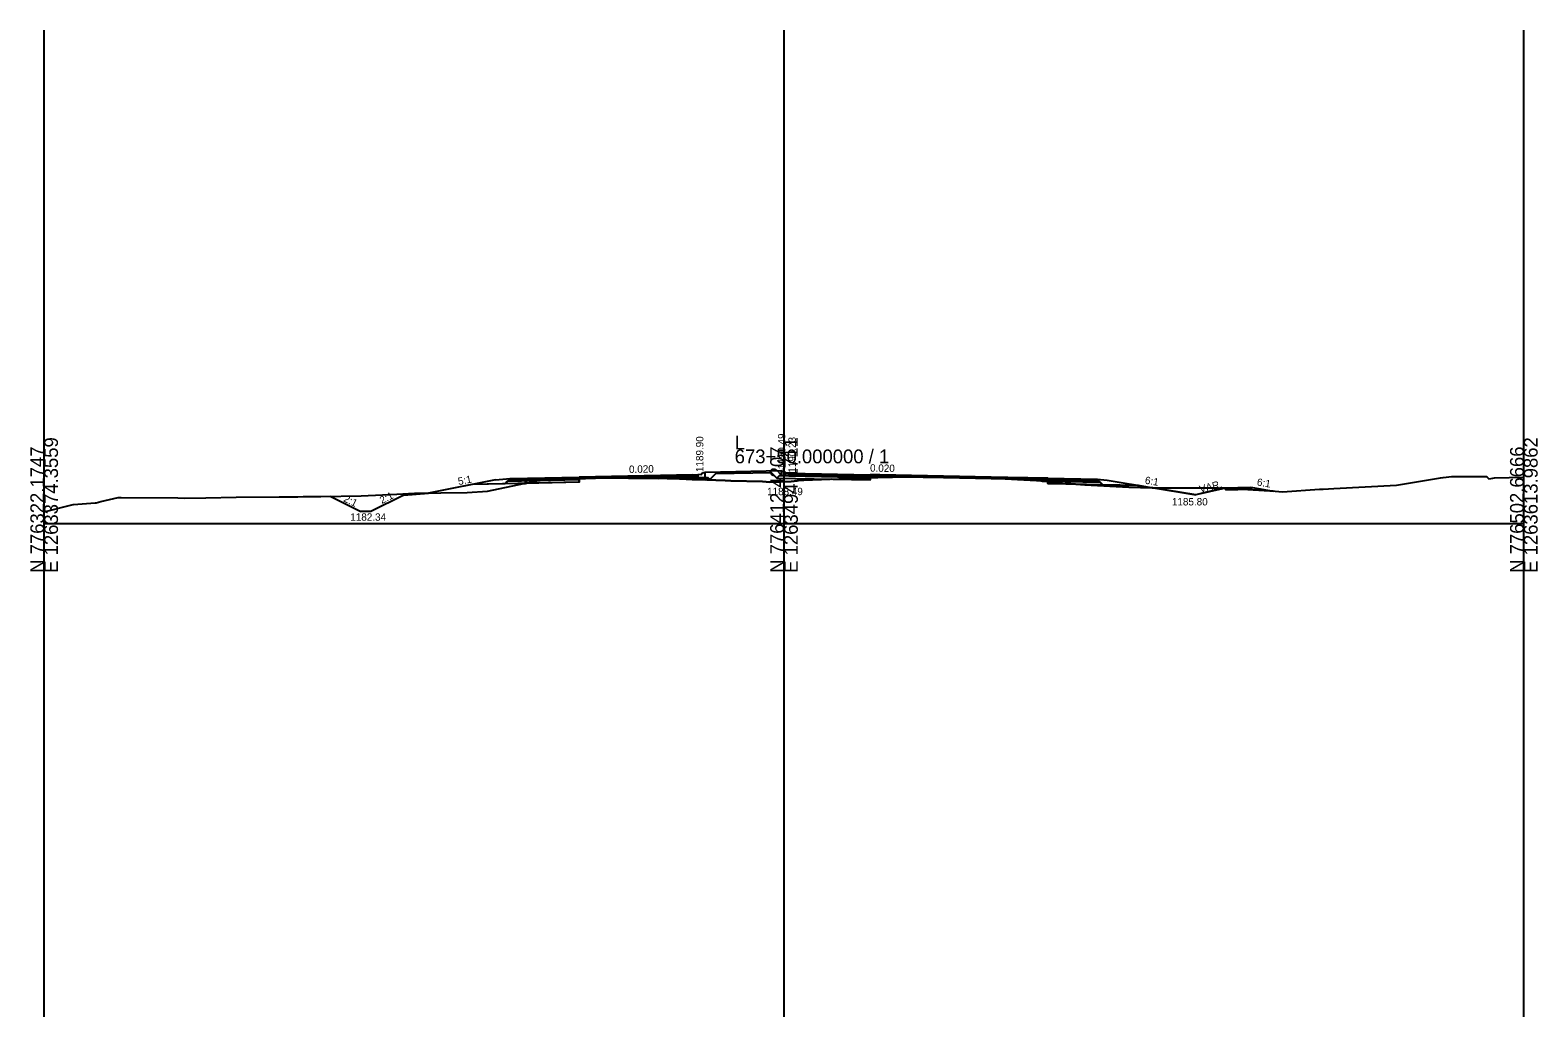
# Model space of a CAD drawing. Extents: x -41 to 1262860, y -100 to 777489.
# Drawn here: x 497.2 to 802.8, y 335 to 535 of the extents above; entities that cross this region are included whole.
import ezdxf

# ---------------------------------------------------------------- set-up
doc = ezdxf.new("R2010")
doc.units = 0
for name, color, linetype in [('Exist Cross Section Cell', 7, 'Continuous'), ('Exist XS Center Line Elevation Label', 7, 'Continuous'), ('Exist XS Ground Line', 7, 'Continuous'), ('Prop CMT Pvmt Concrete', 7, 'Continuous'), ('Prop CMT Pvmt Course 1', 7, 'Continuous'), ('Prop CMT Pvmt Course 4', 7, 'Continuous'), ('Prop CMT Pvmt Surface', 7, 'Continuous'), ('Prop CMT Shld Paved Course 1', 7, 'Continuous'), ('Prop CMT Shld Paved Course 2', 7, 'Continuous'), ('Prop CMT Shld Paved Course 4', 7, 'Continuous'), ('Prop CMT Subgrade Earthwork', 7, 'Continuous'), ('Prop Conc Curb and Gutter', 7, 'Continuous'), ('Prop Conc Island Cover', 7, 'Continuous'), ('Prop XS Ditch Standard Text', 7, 'Continuous'), ('Prop XS Earthwork Shape', 7, 'Continuous'), ('Prop XS Elevation Labels', 7, 'Continuous'), ('Prop XS Exc Vertical Line 1', 7, 'Continuous'), ('Prop XS Exc Vertical Line 2', 7, 'Continuous'), ('Prop XS Exc Vertical Line 3', 7, 'Continuous'), ('Prop XS Finish Grade', 7, 'Continuous'), ('Prop XS Hydro Elevations', 7, 'Continuous'), ('Prop XS SE Text', 7, 'Continuous'), ('Prop XS Side Slope Text', 7, 'Continuous'), ('Scratch_Level_1', 7, 'Continuous'), ('Scratch_Level_4', 7, 'Continuous'), ('Scratch_Level_6', 7, 'Continuous')]:
    doc.layers.add(name, color=color, linetype=linetype)

msp = doc.modelspace()

# ---------------------------------------------------------------- linework, layer by layer
at = {"layer": 'Exist Cross Section Cell'}
for p, q in [((650, 435), (650, 450)), ((500, 435), (650, 435)), ((650, 435), (800, 435))]:
    msp.add_line(p, q, dxfattribs=at)
at = {"layer": 'Exist XS Ground Line'}
msp.add_lwpolyline([(500, 437.38), (505.86, 438.85), (505.98, 438.88), (510.34, 439.19), (510.56, 439.22), (511.46, 439.43), (514.98, 440.26), (515.59, 440.29), (527.1, 440.21), (528.55, 440.16), (532.75, 440.21), (538.9, 440.35), (547.62, 440.38), (551.4, 440.43), (552.51, 440.45), (553.07, 440.46), (556.09, 440.47), (564.29, 440.64), (571.47, 440.93), (575.09, 441.13), (580.43, 441.2), (585.74, 441.3), (589.89, 441.58), (597.25, 443.08), (598.82, 443.4), (599.8, 443.62), (600.53, 443.72), (602.63, 444.02), (604.55, 444.05), (607.67, 444.05), (609.75, 444.15), (611.37, 444.23), (618.5, 444.2), (623.79, 444.16), (628.84, 444.03), (636.2, 443.81), (638.05, 443.71), (639.25, 443.65), (645.61, 443.51), (647.13, 443.4), (651.42, 443.53), (652.68, 443.68), (652.95, 443.7), (654.04, 443.78), (664.67, 444.21), (666.04, 444.27), (674.94, 444.44), (678.23, 444.52), (687.71, 444.37), (688.98, 444.35), (689.89, 444.34), (691.01, 444.28), (701.17, 443.73), (701.42, 443.71), (702.09, 443.63), (706.45, 443.15), (707.36, 443.09), (710.97, 442.82), (719.92, 442.37), (724.67, 442.26), (730.63, 442.21), (737.9, 442.24), (740.67, 442.11), (749.56, 441.56), (751.1, 441.45), (758.57, 441.94), (759.3, 441.99), (761.46, 442.11), (774.21, 442.76), (781.1, 443.89), (783.13, 444.25), (783.61, 444.33), (785.38, 444.56), (787.56, 444.55), (792.38, 444.55), (792.57, 444.37), (792.88, 444.05), (793.71, 444.21), (794.04, 444.28), (800, 444.4)], dxfattribs=at)
at = {"layer": 'Prop CMT Pvmt Concrete'}
for p, q in [((739.5, 442.17), (744.5, 442.27)), ((739.5, 442.17), (739.5, 441.83)), ((739.5, 441.83), (744.51, 441.93)), ((744.5, 442.27), (744.5, 441.93))]:
    msp.add_line(p, q, dxfattribs=at)
at = {"layer": 'Prop CMT Pvmt Course 1'}
for p, q in [((631.5, 444.61), (632.5, 444.63)), ((632.5, 444.63), (632.5, 444.88)), ((650.99, 445.21), (650.99, 444.96)), ((650.99, 444.96), (667.5, 444.63))]:
    msp.add_line(p, q, dxfattribs=at)
for points in [[(608.5, 444.4), (608.5, 444.15), (631.5, 444.61), (631.5, 444.61), (631.5, 444.86), (631.5, 444.86), (631.5, 444.86), (608.5, 444.4), (608.5, 444.4)], [(703.5, 444.16), (703.5, 444.16), (695.36, 444.33), (695.36, 444.33), (695.26, 444.33), (695.26, 444.33), (669.41, 444.85), (669.41, 444.85), (669.18, 444.85), (669.18, 444.85), (668.83, 444.86), (668.83, 444.86), (668.4, 444.87), (668.4, 444.87), (667.95, 444.88), (667.95, 444.88), (667.95, 444.88), (667.54, 444.88), (667.5, 444.88), (667.5, 444.88), (667.5, 444.63), (667.54, 444.63), (667.95, 444.63), (667.95, 444.63), (667.95, 444.63), (668.4, 444.62), (668.4, 444.62), (668.83, 444.61), (668.83, 444.61), (669.18, 444.6), (669.18, 444.6), (669.41, 444.6), (669.41, 444.6), (695.26, 444.08), (695.26, 444.08), (695.36, 444.08), (695.36, 444.08), (703.5, 443.91), (703.5, 444.16)]]:
    msp.add_lwpolyline(points, dxfattribs=at)
at = {"layer": 'Prop CMT Pvmt Course 4'}
for p in [(593.9, 443.53), (608.5, 443.36)]:
    msp.add_line(p, (593.44, 443.06), dxfattribs=at)
at = {"layer": 'Prop CMT Pvmt Surface'}
for p, q in [((594.5, 444.12), (608.5, 444.4)), ((608.5, 444.4), (631.5, 444.86)), ((631.5, 444.86), (632.5, 444.88)), ((650.99, 445.21), (667.5, 444.88)), ((667.5, 444.88), (703.5, 444.16)), ((703.5, 444.16), (713.5, 443.96))]:
    msp.add_line(p, q, dxfattribs=at)
at = {"layer": 'Prop CMT Shld Paved Course 1'}
for p, q in [((608.5, 444.15), (594.24, 443.87)), ((594.5, 444.12), (594.24, 443.87)), ((604.5, 444.32), (604.5, 444.32)), ((608.5, 444.4), (608.5, 444.15)), ((608.5, 444.15), (608.5, 444.15)), ((703.5, 444.16), (703.5, 443.91)), ((703.5, 443.91), (703.5, 443.91)), ((703.5, 443.91), (713.76, 443.71)), ((707.5, 444.08), (707.5, 444.08)), ((713.76, 443.71), (713.5, 443.96))]:
    msp.add_line(p, q, dxfattribs=at)
at = {"layer": 'Prop CMT Shld Paved Course 2'}
for p, q in [((593.9, 443.53), (594.24, 443.87)), ((608.5, 443.82), (593.9, 443.53)), ((603.9, 443.73), (603.9, 443.73)), ((603.9, 443.73), (603.9, 443.73)), ((609.75, 444.18), (608.5, 444.15)), ((608.5, 444.15), (608.5, 443.82)), ((608.5, 444.15), (608.5, 444.15)), ((608.5, 444.15), (608.5, 444.09)), ((608.5, 444.09), (609.75, 444.15)), ((608.5, 443.82), (608.5, 443.82)), ((611.37, 444.21), (609.75, 444.18)), ((609.75, 444.15), (610.73, 444.2)), ((609.75, 444.18), (609.75, 444.18)), ((609.75, 444.15), (609.75, 444.15)), ((610.73, 444.2), (611.37, 444.21)), ((610.73, 444.2), (610.73, 444.2)), ((618.5, 444.35), (611.37, 444.21)), ((611.37, 444.21), (612.19, 444.23)), ((611.37, 444.21), (611.37, 444.21)), ((612.19, 444.23), (612.19, 444.23)), ((612.19, 444.23), (612.19, 444.23)), ((612.19, 444.23), (618.5, 444.2)), ((623.79, 444.46), (618.5, 444.35)), ((618.5, 444.35), (618.5, 444.35)), ((618.5, 444.2), (618.5, 444.2)), ((618.5, 444.2), (623.79, 444.16)), ((628.84, 444.56), (623.79, 444.46)), ((623.79, 444.16), (624.52, 444.14)), ((624.52, 444.14), (628.84, 444.23)), ((624.52, 444.14), (624.52, 444.14)), ((631.5, 444.61), (628.84, 444.56)), ((628.84, 444.56), (628.84, 444.56)), ((628.84, 444.23), (631.5, 444.28)), ((628.84, 444.23), (628.84, 444.23)), ((631.5, 444.28), (631.5, 444.61)), ((631.5, 444.61), (631.5, 444.61)), ((631.5, 444.28), (632.5, 444.3)), ((632.5, 444.63), (632.5, 444.3)), ((650.99, 444.63), (650.99, 444.96)), ((650.99, 444.63), (667.5, 444.3)), ((667.5, 444.3), (667.5, 444.63)), ((667.5, 444.63), (667.5, 444.63)), ((667.5, 444.63), (667.5, 444.63)), ((667.5, 444.63), (667.54, 444.63)), ((667.54, 444.3), (667.5, 444.3)), ((667.54, 444.63), (667.95, 444.63)), ((667.67, 444.3), (667.54, 444.3)), ((667.95, 444.3), (667.67, 444.3)), ((667.67, 444.3), (667.67, 444.3)), ((667.67, 444.3), (667.67, 444.3)), ((667.95, 444.63), (667.95, 444.63)), ((667.95, 444.63), (668.4, 444.62)), ((668.4, 444.31), (667.95, 444.3)), ((668.4, 444.62), (668.4, 444.62)), ((668.4, 444.62), (668.83, 444.61)), ((668.83, 444.32), (668.4, 444.31)), ((668.4, 444.31), (668.4, 444.31)), ((668.83, 444.61), (668.83, 444.61)), ((668.83, 444.61), (669.18, 444.6)), ((669.18, 444.33), (668.83, 444.32)), ((668.83, 444.32), (668.83, 444.32)), ((669.18, 444.6), (669.18, 444.6)), ((669.18, 444.6), (669.41, 444.6)), ((669.41, 444.33), (669.18, 444.33)), ((669.18, 444.33), (669.18, 444.33)), ((669.41, 444.6), (669.41, 444.6)), ((669.41, 444.6), (674.94, 444.49)), ((674.94, 444.44), (669.41, 444.33)), ((669.41, 444.33), (669.41, 444.33)), ((674.94, 444.49), (674.94, 444.49)), ((674.94, 444.49), (674.94, 444.49)), ((674.94, 444.49), (678.23, 444.42)), ((675.98, 444.47), (674.94, 444.44)), ((674.94, 444.44), (674.94, 444.44)), ((674.94, 444.44), (674.94, 444.44)), ((678.23, 444.42), (675.98, 444.47)), ((675.98, 444.47), (675.98, 444.47)), ((687.71, 444.23), (678.23, 444.42)), ((678.23, 444.42), (678.23, 444.42)), ((678.23, 444.42), (678.23, 444.42)), ((678.23, 444.42), (687.71, 444.23)), ((688.98, 444.21), (687.71, 444.23)), ((687.71, 444.23), (687.71, 444.23)), ((687.71, 444.23), (687.71, 444.23)), ((687.71, 444.23), (688.98, 444.21)), ((689.89, 444.19), (688.98, 444.21)), ((688.98, 444.21), (689.89, 444.19)), ((691.01, 444.16), (689.89, 444.19)), ((689.89, 444.19), (691.01, 444.16)), ((694.44, 444.1), (691.01, 444.16)), ((691.01, 444.16), (691.01, 444.16)), ((691.01, 444.16), (691.01, 444.16)), ((691.01, 444.16), (691.01, 444.16)), ((691.01, 444.16), (695.26, 444.08)), ((695.26, 444.05), (694.44, 444.1)), ((694.44, 444.1), (694.44, 444.1)), ((695.26, 444.08), (695.36, 444.08)), ((695.36, 444.05), (695.26, 444.05)), ((695.36, 444.08), (695.36, 444.08)), ((695.36, 444.08), (701.17, 443.96)), ((701.17, 443.73), (695.36, 444.05)), ((695.36, 444.05), (695.36, 444.05)), ((701.17, 443.96), (701.17, 443.96)), ((701.17, 443.96), (701.17, 443.96)), ((701.17, 443.96), (701.42, 443.96)), ((701.42, 443.71), (701.17, 443.73)), ((701.17, 443.73), (701.17, 443.73)), ((701.17, 443.73), (701.17, 443.73)), ((701.42, 443.96), (702.09, 443.94)), ((702.09, 443.63), (701.42, 443.71)), ((702.09, 443.94), (702.09, 443.94)), ((702.09, 443.94), (702.09, 443.94)), ((702.09, 443.94), (703.5, 443.91)), ((702.36, 443.6), (702.09, 443.63)), ((702.09, 443.63), (702.09, 443.63)), ((703.5, 443.58), (702.36, 443.6)), ((702.36, 443.6), (702.36, 443.6)), ((702.36, 443.6), (702.36, 443.6)), ((703.5, 443.91), (703.5, 443.58)), ((703.5, 443.91), (703.5, 443.91)), ((703.5, 443.91), (703.5, 443.91)), ((703.5, 443.91), (703.5, 443.58)), ((703.5, 443.58), (703.5, 443.58)), ((703.5, 443.58), (714.1, 443.37)), ((703.5, 443.58), (703.5, 443.58)), ((714.1, 443.37), (713.76, 443.71))]:
    msp.add_line(p, q, dxfattribs=at)
at = {"layer": 'Prop CMT Shld Paved Course 4'}
for p, q in [((597.4, 443.6), (597.9, 443.61)), ((603.9, 443.73), (603.9, 443.73)), ((608.5, 443.82), (608.5, 443.36)), ((628.84, 444.03), (624.52, 444.14)), ((628.84, 444.03), (631.5, 443.95)), ((631.5, 443.82), (631.5, 444.28)), ((631.5, 443.82), (634.95, 443.89)), ((632.5, 444.3), (634.5, 444.34)), ((634.5, 444.34), (634.95, 443.89)), ((648.99, 444.67), (648.55, 444.22)), ((648.55, 444.22), (667.5, 443.84)), ((650.99, 444.63), (648.99, 444.67)), ((667.5, 444.3), (667.5, 443.84)), ((667.67, 444.3), (667.5, 444.29)), ((702.36, 443.6), (703.5, 443.48)), ((703.5, 443.58), (703.5, 443.12)), ((714.56, 442.9), (714.1, 443.37)), ((703.5, 443.12), (714.56, 442.9))]:
    msp.add_line(p, q, dxfattribs=at)
at = {"layer": 'Prop CMT Subgrade Earthwork'}
for p, q in [((608.5, 443.36), (586.71, 442.93)), ((608.5, 443.36), (608.5, 444.09)), ((631.5, 443.82), (631.5, 443.95)), ((634.95, 443.89), (631.5, 443.82)), ((634.95, 443.89), (636.44, 445.38)), ((648.55, 444.22), (647.16, 445.61)), ((648.55, 444.22), (667.5, 443.84)), ((667.5, 443.84), (667.5, 444.29)), ((703.5, 443.48), (703.5, 443.12)), ((703.5, 443.12), (721.78, 442.76))]:
    msp.add_line(p, q, dxfattribs=at)
at = {"layer": 'Prop Conc Curb and Gutter'}
for p, q in [((633.19, 444.9), (632.5, 444.88)), ((632.5, 444.88), (632.5, 444.3)), ((632.5, 444.3), (634, 444.33)), ((633.25, 444.98), (633.25, 444.96)), ((634, 445.33), (633.35, 445.11)), ((634, 444.33), (634, 445.33)), ((634, 444.33), (634, 444.33)), ((649.49, 445.66), (650.15, 445.44)), ((649.49, 444.66), (649.49, 445.66)), ((650.99, 444.63), (649.49, 444.66)), ((650.24, 445.31), (650.24, 445.29)), ((650.31, 445.23), (650.99, 445.21)), ((650.99, 444.63), (650.99, 445.21))]:
    msp.add_line(p, q, dxfattribs=at)
for centre, radius, start, end in [((633.19, 444.96), 0.0625, 271.1458, 360), ((633.4, 444.98), 0.146, 108.435, 180), ((650.1, 445.31), 0.146, 0, 71.565), ((650.31, 445.29), 0.0625, 180, 268.8542)]:
    msp.add_arc(centre, radius, start, end, dxfattribs=at)
at = {"layer": 'Prop Conc Island Cover'}
for p, q in [((649.49, 445.66), (634, 445.33)), ((634, 445.07), (634, 445.07))]:
    msp.add_line(p, q, dxfattribs=at)
at = {"layer": 'Prop XS Earthwork Shape'}
for points in [[(602.63, 444.02), (604.55, 444.05), (607.67, 444.05), (608.5, 444.09), (608.5, 443.36), (597.57, 443.14), (598.82, 443.4), (599.8, 443.62), (600.53, 443.72)], [(634.06, 443.87), (631.5, 443.82), (631.5, 443.95)], [(636.19, 445.13), (647.4, 445.37), (648.55, 444.22), (659.57, 444), (654.04, 443.78), (652.95, 443.7), (652.68, 443.68), (651.42, 443.53), (647.13, 443.4), (645.61, 443.51), (639.25, 443.65), (638.05, 443.71), (636.2, 443.81), (634.06, 443.87), (634.95, 443.89)], [(664.67, 444.21), (666.04, 444.27), (667.5, 444.29), (667.5, 443.84), (659.57, 444)], [(706.45, 443.15), (707.36, 443.09), (708.15, 443.03), (703.5, 443.12), (703.5, 443.48)], [(597.57, 443.14), (593.44, 443.06), (586.71, 442.93), (577.9, 441.17), (580.43, 441.2), (585.74, 441.3), (589.89, 441.58), (597.25, 443.08)], [(714.56, 442.9), (721.78, 442.76), (724.78, 442.26), (724.67, 442.26), (719.92, 442.37), (710.97, 442.82), (708.15, 443.03)], [(724.78, 442.26), (730.63, 442.21), (737.9, 442.24), (739.5, 442.17), (733.5, 440.8)], [(739.5, 442.17), (744.5, 442.27), (745, 442.28), (749.16, 441.58), (740.67, 442.11)]]:
    msp.add_lwpolyline(points, close=True, dxfattribs=at)
at = {"layer": 'Prop XS Exc Vertical Line 1'}
msp.add_line((500, 335), (500, 535), dxfattribs=at)
at = {"layer": 'Prop XS Exc Vertical Line 2'}
msp.add_line((650, 335), (650, 535), dxfattribs=at)
at = {"layer": 'Prop XS Exc Vertical Line 3'}
msp.add_line((800, 335), (800, 535), dxfattribs=at)
at = {"layer": 'Prop XS Finish Grade'}
for p, q in [((591.5, 443.88), (577.9, 441.17)), ((591.5, 443.88), (594.5, 444.12)), ((594.5, 444.12), (593.44, 443.06)), ((713.5, 443.96), (715.5, 443.8)), ((713.5, 443.96), (714.56, 442.9)), ((715.5, 443.8), (733.5, 440.8)), ((557.99, 440.51), (564.2, 437.4)), ((572.9, 440.75), (566.2, 437.4)), ((572.9, 440.75), (577.9, 441.17)), ((739, 442.16), (733.5, 440.8)), ((739, 442.16), (744.5, 442.27)), ((744.5, 442.27), (745, 442.28)), ((745, 442.28), (749.16, 441.58)), ((566.2, 437.4), (564.2, 437.4))]:
    msp.add_line(p, q, dxfattribs=at)
at = {"layer": 'Scratch_Level_1'}
msp.add_lwpolyline([(744.5, 442.27), (739.5, 442.17), (738.34, 442.22)], dxfattribs=at)
at = {"layer": 'Scratch_Level_4'}
msp.add_line((800, 335), (800, 535), dxfattribs=at)
at = {"layer": 'Scratch_Level_6'}
msp.add_line((500, 335), (500, 535), dxfattribs=at)

# ---------------------------------------------------------------- texts
at = {"layer": 'Exist Cross Section Cell'}
for s, p in [('L', (640, 450)), ('673+50.000000 / 1', (640, 447.2))]:
    msp.add_text(s, height=2.8, dxfattribs=at).set_placement(p)
for s, p in [('N 776322.1747', (500, 425)), ('E 1263374.3559', (502.8, 425)), ('N 776412.4207', (650, 425)), ('E 1263494.1711', (652.8, 425)), ('N 776502.6666', (800, 425)), ('E 1263613.9862', (802.8, 425))]:
    msp.add_text(s, height=2.8, rotation=90, dxfattribs=at).set_placement(p)
at = {"layer": 'Exist XS Center Line Elevation Label'}
msp.add_text('1188.49', height=1.5, dxfattribs=at).set_placement((646.57, 440.74))
at = {"layer": 'Prop XS Ditch Standard Text'}
for s, p in [('1185.80', (728.65, 438.66)), ('1182.34', (562.07, 435.56))]:
    msp.add_text(s, height=1.5, dxfattribs=at).set_placement(p)
at = {"layer": 'Prop XS Elevation Labels'}
for s, p in [('1189.90', (633.65, 445.43)), ('1190.23', (652.4, 445.29))]:
    msp.add_text(s, height=1.5, rotation=90, dxfattribs=at).set_placement(p)
at = {"layer": 'Prop XS Hydro Elevations'}
msp.add_text('1190.49', height=1.5, rotation=90, dxfattribs=at).set_placement((650.28, 446))
at = {"layer": 'Prop XS SE Text'}
for rotation, p in [(1.1458, (618.59, 445.24)), (358.8542, (667.43, 445.52))]:
    msp.add_text('0.020', height=1.5, rotation=rotation, dxfattribs=at).set_placement(p)
at = {"layer": 'Prop XS Side Slope Text'}
for s, rotation, p in [('5:1', 11.3099, (584.05, 442.77)), ('6:1', 350.5377, (723.09, 443.08)), ('VAR.', 14.2871, (734.42, 441.2)), ('6:1', 350.5377, (745.8, 442.72)), ('2:1', 333.6935, (560.56, 439.55)), ('2:1', 26.5651, (568.48, 438.93))]:
    msp.add_text(s, height=1.5, rotation=rotation, dxfattribs=at).set_placement(p)

doc.saveas('drawing.dxf')
